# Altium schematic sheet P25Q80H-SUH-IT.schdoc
size 127 x 101 mm
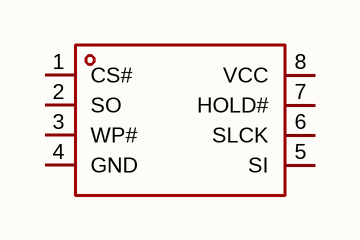
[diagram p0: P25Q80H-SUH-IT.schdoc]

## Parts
U?  p25q80h-suh-it  [SOP-8_L5.3-W5.3-P1.27-LS8.0-BL]  (value not drawn)

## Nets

Not connected (* = marked no-connect by the designer): U? 1(CS#) 2(SO) 3(WP#) 4(GND) 5(SI) 6(SLCK) 7(HOLD#) 8(VCC)

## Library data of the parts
U? = p25q80h-suh-it: 接口类型:SPI;存储容量:8Mbit;时钟频率(fc):104MHz;; Manufacturer: PUYA(普冉); AddInBom: yes; ModelId: e456afcfff5840a795bdd4917416584f; ModelName: SOP-8_L5.2-W5.3-H2.1-LS7.9-P1.27; ModelTransform: 311.024,204.724,0,90,0,0,0,0.0005,0; Interface: SPI; Memory Size: 8Mbit; Clock Frequency: 104MHz; Voltage - Supply: 2.3V~3.6V; Standby Supply Current: 6uA; Program / Erase Cycles: 100000次; Page Programming Time (Tpp): 2ms; Data Retention - TDR (Year): 20年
